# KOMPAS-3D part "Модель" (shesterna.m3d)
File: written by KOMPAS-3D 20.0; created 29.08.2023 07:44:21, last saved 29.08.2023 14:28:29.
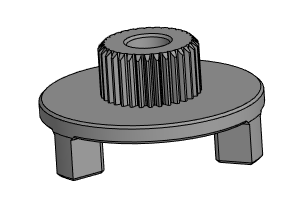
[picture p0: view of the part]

Document properties: Полное имя файла: D:\Шестерня стеклоподъемника.m3d

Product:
- Part/product: Модель
    Масса: 0.057792
    Комментарий: Модуль генерации 3D-моделей программы <Валы и механические передачи 2D>
    source file: Модель.cdw
  - Component [billet]: Модель  | Масса: 0.0146721; Комментарий: Модуль генерации 3D-моделей программы <Валы и механические передачи 2D>; source file: Модель.m3d
  - Body: Тело 2
      Масса: 0.0469466
  - Body: Тело 1
      Масса: 0.0469466

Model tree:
1. Эскиз:1
2. Внеш. контур, ступень 1: Шестерня Z=32, L=10
     Расстояние 2 = 10; Смещение 2 = 10
3. Внеш. контур, ступень 1: Шестерня Z=32, L=10, средняя плоскость  (labels: Внеш. контур, ступень 1: Шестерня Z=32, L=10)
     Расстояние = 5
4. Внеш. контур, ступень 1: Шестерня Z=32, L=10, плоскость межосевого расстояния
     Расстояние = 17.0686
5. Ось операции:1
6. Внеш. контур, ступень 1: Шестерня Z=32, L=10, ЛСК зубчатого венца  (with: Плоскость XY, Плоскость ZX, Плоскость ZY, Ось X, Ось Y, Ось Z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)
     Ось X. X = 1; Ось Y. Y = 1; Ось Z. Z = 1
7. Точка:1
8. Точка:2
     X = 10; Координата X = 10
9. Осевая линия:1
10. Эскиз:2  (labels: Внеш. контур, ступень 1: Шестерня Z=32, L=10)
11. Элемент выдавливания:2
     Расстояние 1 = 3.5
12. Эскиз:3  (with: Элемент выдавливания:2)
13. Элемент выдавливания:3
     Расстояние 1 = 8.5
14. Массив по концентрической сетке:1  (with: Элемент выдавливания:3, Элемент выдавливания:2)  (3 pattern instances)
     Шаг 2 = 360
15. Скругление:1  (with: Элемент выдавливания:3)
     Радиус = 1
16. Скругление:2  (with: Элемент выдавливания:3)
     Радиус = 1
17. Скругление:3  (with: Элемент выдавливания:3)
     Радиус = 1
18. Скругление:4  (with: Элемент выдавливания:3)
     Радиус = 1
19. Скругление:5  (with: Элемент выдавливания:3)
     Радиус = 1
20. Скругление:6  (with: Элемент выдавливания:3)
     Радиус = 1
21. Эскиз:5  (with: Элемент выдавливания:2)
22. Элемент выдавливания:5
     Расстояние 1 = 10
23. Эскиз:8  (labels: Внеш. контур, ступень 1: Шестерня Z=32, L=10)
24. Элемент выдавливания:9
     Расстояние 2 = 15
25. Фаска:1  (with: Элемент выдавливания:9)
     Угол = 45; Длина 1 = 0.5; Длина 2 = 0.5
26. Фаска:2  (with: Элемент выдавливания:9)
     Угол = 45; Длина 1 = 0.5; Длина 2 = 0.5
27. Фаска:3  (with: Элемент выдавливания:2)
     Угол = 45; Длина 1 = 0.5; Длина 2 = 0.5
28. Фаска:6  (with: Элемент выдавливания:3)
     Угол = 45; Длина 1 = 0.5; Длина 2 = 0.5
29. Фаска:7  (with: Элемент выдавливания:3)
     Угол = 45; Длина 1 = 0.5; Длина 2 = 0.5
30. Фаска:8  (with: Элемент выдавливания:3)
     Угол = 45; Длина 1 = 0.5; Длина 2 = 0.5
31. Фаска:9  (with: Элемент выдавливания:2)
     Угол = 45; Длина 1 = 0.5; Длина 2 = 0.5
32. Фаска:10  (with: Элемент выдавливания:2)
     Угол = 45; Длина 1 = 0.5; Длина 2 = 0.5
33. Фаска:11  (with: Элемент выдавливания:2)
     Угол = 45; Длина 1 = 0.5; Длина 2 = 0.5
34. Фаска:12  (with: Элемент выдавливания:3)
     Угол = 45; Длина 1 = 0.5; Длина 2 = 0.5
35. Фаска:13  (with: Элемент выдавливания:3)
     Угол = 45; Длина 1 = 0.5; Длина 2 = 0.5
36. Фаска:14  (with: Элемент выдавливания:3)
     Угол = 45; Длина 1 = 0.5; Длина 2 = 0.5

Referenced files in D:\: Модель.m3d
